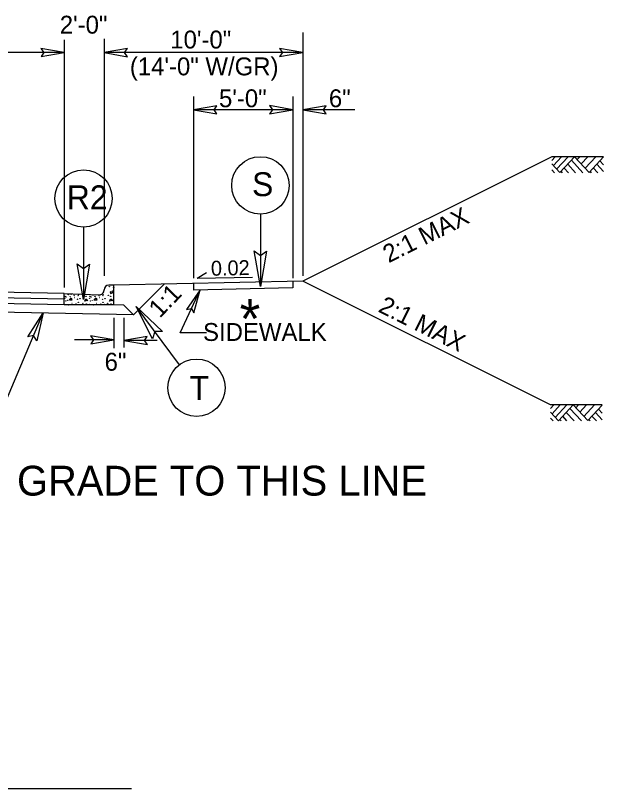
# Model space of a CAD drawing. Extents: x 1904401 to 1905163, y 193929 to 194736.
# Drawn here: x 1904615.48 to 1904645.06, y 194580.17 to 194619.06 of the extents above; entities that cross this region are included whole.
import ezdxf

# ---------------------------------------------------------------- set-up
doc = ezdxf.new("R2010")
doc.units = 0
for name, color, linetype in [('Default', 7, 'Continuous'), ('Prop Lane Arrow CELL', 7, 'Continuous'), ('Typical Arrow Superelevation CELL', 7, 'Continuous'), ('Typical Berm CELL', 7, 'Continuous'), ('Typical Curb CELL', 7, 'Continuous'), ('Typical Hinge Slope Arterial CELL', 7, 'Continuous'), ('Typical ID Circle CELL', 7, 'Continuous'), ('Typical Pavement Slope CELL', 7, 'Continuous'), ('Typical Terminator CELL', 7, 'Continuous'), ('Typical Text ID Circle CELL', 7, 'Continuous')]:
    doc.layers.add(name, color=color, linetype=linetype)

msp = doc.modelspace()

# ---------------------------------------------------------------- linework, layer by layer
at = {"layer": 'Default'}
for p, q in [((1904617.938, 194617.836), (1904617.938, 194605.379)), ((1904624.438, 194614.985), (1904624.438, 194605.85)), ((1904629.438, 194614.985), (1904629.438, 194605.85))]:
    msp.add_line(p, q, dxfattribs=at)
at = {"layer": 'Prop Lane Arrow CELL'}
for p, q in [((1904629.938, 194618.199), (1904629.938, 194605.957)), ((1904619.938, 194617.876), (1904619.938, 194605.957)), ((1904617.938, 194617.188), (1904603.938, 194617.188)), ((1904629.938, 194617.188), (1904619.938, 194617.188)), ((1904629.438, 194614.985), (1904629.438, 194605.957)), ((1904629.438, 194614.313), (1904624.438, 194614.313)), ((1904632.542, 194614.313), (1904629.938, 194614.313)), ((1904642.627, 194611.951), (1904642.457, 194611.768)), ((1904642.948, 194611.951), (1904642.533, 194611.507)), ((1904643.281, 194611.951), (1904642.7, 194611.328)), ((1904643.603, 194611.95), (1904642.862, 194611.154)), ((1904644.334, 194611.164), (1904643.603, 194611.95)), ((1904643.867, 194611.951), (1904643.734, 194611.808)), ((1904644.268, 194611.951), (1904643.936, 194611.592)), ((1904644.666, 194611.951), (1904644.134, 194611.378)), ((1904645.058, 194611.943), (1904644.334, 194611.164)), ((1904642.862, 194611.154), (1904642.458, 194611.589)), ((1904643.654, 194611.146), (1904643.254, 194611.575)), ((1904644.024, 194611.146), (1904643.438, 194611.774)), ((1904645.058, 194611.209), (1904644.716, 194611.575)), ((1904645.058, 194611.542), (1904644.872, 194611.742)), ((1904642.592, 194611.146), (1904642.458, 194611.289)), ((1904642.993, 194611.146), (1904642.924, 194611.22)), ((1904643.288, 194611.146), (1904643.071, 194611.379)), ((1904644.459, 194611.146), (1904644.388, 194611.222)), ((1904644.769, 194611.146), (1904644.543, 194611.389)), ((1904623.77, 194603.086), (1904624.766, 194605.25)), ((1904613.308, 194595.673), (1904616.872, 194604.091)), ((1904620.437, 194603.853), (1904620.437, 194602.314)), ((1904620.937, 194603.852), (1904620.937, 194602.354)), ((1904625.087, 194603.086), (1904623.77, 194603.086)), ((1904620.437, 194602.736), (1904618.447, 194602.736)), ((1904622.609, 194602.708), (1904620.937, 194602.708)), ((1904642.56, 194599.465), (1904642.39, 194599.282)), ((1904642.88, 194599.465), (1904642.466, 194599.021)), ((1904643.213, 194599.465), (1904642.633, 194598.842)), ((1904643.535, 194599.464), (1904642.794, 194598.668)), ((1904644.266, 194598.678), (1904643.535, 194599.464)), ((1904643.799, 194599.465), (1904643.666, 194599.322)), ((1904644.201, 194599.465), (1904643.868, 194599.106)), ((1904644.599, 194599.465), (1904644.066, 194598.892)), ((1904644.99, 194599.457), (1904644.266, 194598.678)), ((1904642.794, 194598.668), (1904642.39, 194599.103)), ((1904643.586, 194598.66), (1904643.186, 194599.089)), ((1904643.956, 194598.66), (1904643.37, 194599.288)), ((1904644.99, 194598.723), (1904644.648, 194599.089)), ((1904644.99, 194599.056), (1904644.804, 194599.256)), ((1904642.524, 194598.66), (1904642.39, 194598.803)), ((1904642.925, 194598.66), (1904642.856, 194598.734)), ((1904643.22, 194598.66), (1904643.003, 194598.893)), ((1904644.391, 194598.66), (1904644.32, 194598.736)), ((1904644.702, 194598.66), (1904644.475, 194598.903)), ((1904540.042, 194580.172), (1904621.321, 194580.172))]:
    msp.add_line(p, q, dxfattribs=at)
for points in [[(1904645.058, 194611.951), (1904642.458, 194611.951)], [(1904644.99, 194599.465), (1904642.39, 194599.465)]]:
    msp.add_lwpolyline(points, dxfattribs=at)
at = {"layer": 'Typical Arrow Superelevation CELL'}
for q in [(1904625.083, 194606.12), (1904627.41, 194605.892)]:
    msp.add_line((1904624.613, 194605.836), q, dxfattribs=at)
at = {"layer": 'Typical Berm CELL'}
for p, q in [((1904629.938, 194605.691), (1904620.437, 194605.493)), ((1904629.438, 194605.681), (1904629.438, 194605.348)), ((1904624.438, 194605.576), (1904624.438, 194605.243)), ((1904629.438, 194605.348), (1904624.438, 194605.243))]:
    msp.add_line(p, q, dxfattribs=at)
at = {"layer": 'Typical Curb CELL'}
for p, q in [((1904619.937, 194605.243), (1904619.937, 194605.253)), ((1904620.437, 194605.493), (1904620.177, 194605.493)), ((1904620.437, 194604.493), (1904620.437, 194605.493)), ((1904617.938, 194604.493), (1904617.938, 194605.076)), ((1904617.938, 194605.076), (1904619.688, 194605.004)), ((1904618.198, 194604.733), (1904618.284, 194604.852)), ((1904618.284, 194604.852), (1904618.319, 194604.739)), ((1904619.448, 194604.733), (1904619.533, 194604.852)), ((1904619.533, 194604.852), (1904619.568, 194604.739)), ((1904620.247, 194605.16), (1904620.263, 194605.069)), ((1904620.401, 194605.115), (1904620.247, 194605.16)), ((1904620.263, 194605.069), (1904620.401, 194605.115)), ((1904620.437, 194604.493), (1904617.938, 194604.493)), ((1904618.319, 194604.739), (1904618.198, 194604.733)), ((1904618.963, 194604.682), (1904619.026, 194604.796)), ((1904619.129, 194604.721), (1904618.963, 194604.682)), ((1904619.026, 194604.796), (1904619.129, 194604.721)), ((1904619.568, 194604.739), (1904619.448, 194604.733)), ((1904620.212, 194604.682), (1904620.275, 194604.796)), ((1904620.378, 194604.721), (1904620.212, 194604.682)), ((1904620.275, 194604.796), (1904620.378, 194604.721))]:
    msp.add_line(p, q, dxfattribs=at)
for centre in [(1904620.207, 194605.417), (1904620.424, 194605.383), (1904617.954, 194604.83), (1904617.971, 194604.927), (1904618.027, 194604.893), (1904618.136, 194605.018), (1904618.233, 194604.933), (1904618.278, 194605.035), (1904618.427, 194604.972), (1904618.455, 194604.87), (1904618.632, 194604.956), (1904618.649, 194605.006), (1904618.906, 194604.978), (1904619.026, 194604.927), (1904619.203, 194604.83), (1904619.22, 194604.927), (1904619.276, 194604.893), (1904619.385, 194604.987), (1904619.482, 194604.933), (1904619.676, 194604.972), (1904619.705, 194604.87), (1904619.881, 194604.956), (1904619.899, 194605.006), (1904620.155, 194604.978), (1904620.275, 194604.927), (1904620.372, 194605.2), (1904617.948, 194604.522), (1904618.011, 194604.687), (1904618.107, 194604.733), (1904618.159, 194604.499), (1904618.318, 194604.568), (1904618.524, 194604.545), (1904618.604, 194604.785), (1904618.638, 194604.63), (1904618.695, 194604.516), (1904618.73, 194604.813), (1904618.872, 194604.579), (1904619.043, 194604.539), (1904619.197, 194604.522), (1904619.26, 194604.687), (1904619.356, 194604.733), (1904619.408, 194604.499), (1904619.567, 194604.568), (1904619.773, 194604.545), (1904619.853, 194604.785), (1904619.887, 194604.63), (1904619.944, 194604.516), (1904619.979, 194604.813), (1904620.121, 194604.579), (1904620.292, 194604.539)]:
    msp.add_circle(centre, 0.00802, dxfattribs=at)
for centre, start, end in [((1904619.698, 194605.243), 267.6155, 0), ((1904620.177, 194605.253), 90, 180)]:
    msp.add_arc(centre, 0.24, start, end, dxfattribs=at)
at = {"layer": 'Typical Hinge Slope Arterial CELL'}
for p in [(1904642.458, 194611.951), (1904642.39, 194599.465)]:
    msp.add_line(p, (1904629.938, 194605.691), dxfattribs=at)
at = {"layer": 'Typical ID Circle CELL'}
for p, q in [((1904627.801, 194609.066), (1904627.801, 194605.425)), ((1904618.906, 194608.408), (1904618.906, 194604.768)), ((1904623.728, 194601.488), (1904621.558, 194604.411))]:
    msp.add_line(p, q, dxfattribs=at)
for centre in [(1904627.801, 194610.508), (1904618.906, 194609.851), (1904624.588, 194600.33)]:
    msp.add_circle(centre, 1.443, dxfattribs=at)
at = {"layer": 'Typical Pavement Slope CELL'}
for p, q in [((1904617.938, 194605.076), (1904591.938, 194605.596)), ((1904621.42, 194604), (1904622.966, 194605.546)), ((1904617.938, 194604.493), (1904598.432, 194604.883)), ((1904617.938, 194604.785), (1904598.438, 194605.175)), ((1904621.42, 194604), (1904598.423, 194604.46)), ((1904620.937, 194604.483), (1904620.437, 194604.493)), ((1904621.42, 194604), (1904620.937, 194604.483))]:
    msp.add_line(p, q, dxfattribs=at)
at = {"layer": 'Typical Terminator CELL'}
for points in [[(1904616.766, 194616.986), (1904617.938, 194617.188), (1904616.759, 194617.396), (1904616.909, 194617.188)], [(1904621.109, 194617.389), (1904619.938, 194617.188), (1904621.116, 194616.979), (1904620.966, 194617.188)], [(1904628.766, 194616.986), (1904629.938, 194617.188), (1904628.759, 194617.396), (1904628.909, 194617.188)], [(1904625.61, 194614.515), (1904624.438, 194614.313), (1904625.616, 194614.105), (1904625.467, 194614.313)], [(1904628.266, 194614.111), (1904629.438, 194614.313), (1904628.26, 194614.521), (1904628.41, 194614.313)], [(1904631.109, 194614.515), (1904629.938, 194614.313), (1904631.116, 194614.105), (1904630.966, 194614.313)], [(1904628.107, 194607.206), (1904627.801, 194605.425), (1904627.484, 194607.216), (1904627.801, 194606.989)], [(1904619.213, 194606.549), (1904618.906, 194604.768), (1904618.59, 194606.559), (1904618.906, 194606.331)], [(1904624.46, 194604.101), (1904624.766, 194605.25), (1904624.084, 194604.267), (1904624.336, 194604.316)], [(1904616.101, 194602.891), (1904616.872, 194604.091), (1904616.551, 194602.692), (1904616.391, 194602.955)], [(1904622.374, 194602.798), (1904621.558, 194604.411), (1904622.88, 194603.162), (1904622.49, 194603.156)], [(1904619.266, 194602.534), (1904620.437, 194602.736), (1904619.259, 194602.944), (1904619.409, 194602.736)], [(1904622.109, 194602.91), (1904620.937, 194602.708), (1904622.115, 194602.5), (1904621.965, 194602.708)]]:
    msp.add_lwpolyline(points, close=True, dxfattribs=at)

# ---------------------------------------------------------------- texts
at = {"layer": 'Prop Lane Arrow CELL'}
for s, height, p in [('2\'-0"', 0.9, (1904617.71, 194618.142)), ('10\'-0" ', 0.9, (1904623.268, 194617.394)), ('(14\'-0" W/GR)', 0.9, (1904621.234, 194616.044)), ('5\'-0"', 0.9, (1904625.718, 194614.44)), ('6"', 0.9, (1904631.244, 194614.44)), ('*', 2, (1904626.756, 194602.798)), ('SIDEWALK', 0.9, (1904624.916, 194602.685))]:
    msp.add_text(s, height=height, dxfattribs=at).set_placement(p)
for s, height, rotation, p in [('0.02', 0.7499, 1.1462, (1904625.318, 194605.963)), ('1:1', 0.9, 45.8681, (1904622.74, 194603.801)), ('6"', 0.9, 0.0002, (1904619.965, 194601.188)), ('GRADE TO THIS LINE', 1.5, 0.0002, (1904615.56, 194594.907))]:
    msp.add_text(s, height=height, rotation=rotation, dxfattribs=at).set_placement(p)
at = {"layer": 'Typical Hinge Slope Arterial CELL'}
for rotation, p in [(26.565, (1904634.25, 194606.589)), (333.4349, (1904633.675, 194604.174))]:
    msp.add_text('2:1 MAX', height=0.9, rotation=rotation, dxfattribs=at).set_placement(p)
at = {"layer": 'Typical Text ID Circle CELL'}
for s, p in [('S', (1904627.379, 194609.968)), ('R2', (1904618.064, 194609.31)), ('T', (1904624.233, 194599.719))]:
    msp.add_text(s, height=1.2, rotation=360, dxfattribs=at).set_placement(p)

doc.saveas('drawing.dxf')
